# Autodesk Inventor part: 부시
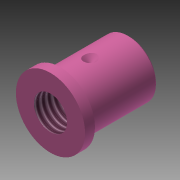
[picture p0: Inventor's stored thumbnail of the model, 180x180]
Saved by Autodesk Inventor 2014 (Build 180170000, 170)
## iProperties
Created: 2019-04
Part Number: 부시
Material: 강철, 연강
Document SubType Name: Modeling
Designer: mduedu
Density: 1 g/cm^3
Appearance: Pink
Author: mduedu
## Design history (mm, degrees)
sketch "스케치1"
  geometry: L1 (0, 0)-(3, 0); L2 (3, 0)-(3, 10.5); L3 (3, 10.5)-(0, 10.5); L4 (0, 10.5)-(0, 0); L5 (3, 0)-(24, 0); L6 (24, 0)-(24, 8.5); L7 (24, 8.5)-(3, 8.5); L8 (3, 8.5)-(3, 0)
  constraints: 16 end point, 4 parallel, 2 horizontal, 2 perpendicular
  dimensions: "d0" = 3 distance of L2.end L3.end; "d2" = 24 distance between parallel lines of L6 L4; "d3" = 17 diameter of L7 L5; "d4" = 21 diameter of L3 L1
revolve "회전1" sketch "스케치1" stored, may be unused: angle "d5" = 90 deg
sketch "스케치2"
  geometry: L1 (3, 8.5)-(24, 8.5) reference; L2 (12, 8.5)-(12, 6.5); L3 (12, 6.5)-(14, 8.5); L4 (0, -10.5)-(0, 10.5) reference; 1 further point
  constraints: 4 end point, 2 point on line, 1 perpendicular
  dimensions: "d6" = 12 distance from line of L2.start L4; "d7" = 2 distance of L2.start L3.end; "d8" = 45 deg angle of L3 L2
revolve "회전2" sketch "스케치2" stored, may be unused: angle "d9" = 90 deg
hole "구멍1" diameter "d12" = 10.106; stored, may be unused: countersink angle "d16" = 90 deg, drill point angle "d18" = 118 deg; dims "d10" = 10, "d11" = 10, "d13" = 39, "d14" = 4, "d15" = 2, "d17" = 8
chamfer "모따기1" distance "d19" = 0.5; stored, may be unused: second distance "d20" = 2, angle "d21" = 45 deg
node "작업점1"
  node "작업 평면1"
  node "작업축1"
workplane "Work Plane2"
  workaxis "Work Axis2"
sketch "Sketch3"
  geometry: L1 (-16, 11.5)-(-15.5, 12) reference; L2 (-15.5, 12)-(-12.553, 12) reference; L3 (-12.553, 12)-(-12.553, -12) reference; L4 (-12.553, -12)-(-18, -12) reference; L5 (-18, -12)-(-18, -9) reference; L6 (-18, -9)-(-16, -9) reference; L7 (-16, -9)-(-16, 11.5) reference; L8 (1, -2)-(1, -9) reference; L9 (1, -9)-(3, -9) reference; L10 (3, -9)-(3, -12) reference; L11 (3, -12)-(-2.447, -12) reference; L12 (-2.447, -12)-(-2.447, 12) reference; L13 (-2.447, 12)-(0.5, 12) reference; L14 (0.5, 12)-(1, 11.5) reference; L15 (1, 11.5)-(1, 2) reference; L16 (1, 2)-(-1, 0) reference; L17 (-1, 0)-(1, -2) reference; L18 (-1, 0)-(1, 2); L19 (-1, 0)-(1, -2); 1 further point
  constraints: 4 end point, 1 collinear, 1 perpendicular
  node "Project Cut Edges1"
node "솔리드1"
other parameters: "d22" = 90 deg
